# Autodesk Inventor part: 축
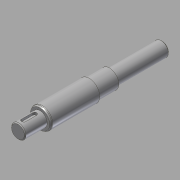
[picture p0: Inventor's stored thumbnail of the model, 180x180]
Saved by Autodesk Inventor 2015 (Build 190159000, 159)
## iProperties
Created: 2019-01
Part Number: 축
Material: 강철, 탄소
Document SubType Name: Modeling
Designer: mduedu
Density: 7.87 g/cm^3
Mass: 452.778 g
Surface Area: 120.904 cm^2
Volume: 57.5322 cm^3
Appearance: 강철
Author: mduedu
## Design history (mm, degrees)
sketch "스케치1"
  geometry: L1 (0, 0)-(26, 0); L2 (26, 0)-(26, 8.5); L3 (26, 8.5)-(0, 8.5); L4 (0, 8.5)-(0, 0); L5 (26, 0)-(84, 0); L6 (84, 0)-(84, 12.5); L7 (84, 12.5)-(26, 12.5); L8 (26, 12.5)-(26, 0); L9 (84, 0)-(108, 0); L10 (108, 0)-(108, 11); L11 (108, 11)-(84, 11); L12 (84, 11)-(84, 0); L13 (108, 0)-(170, 0); L14 (170, 0)-(170, 8.5); L15 (170, 8.5)-(108, 8.5); L16 (108, 8.5)-(108, 0)
  constraints: 32 end point, 8 parallel, 4 horizontal, 4 perpendicular
  dimensions: "d0" = 170 distance between parallel lines of L14 L4; "d2" = 26 distance of L2.end L3.end; "d3" = 24 distance of L10.end L11.end; "d4" = 62 distance of L14.end L15.end; "d5" = 17 diameter of L3 L1; "d6" = 25 diameter of L7 L5; "d7" = 22 diameter of L11 L9; "d8" = 17 diameter of L15 L13
revolve "회전1" sketch "스케치1" stored, may be unused: angle "d9" = 90 deg
node "작업 평면1"
sketch "스케치2" dims "d13" = 18
  geometry: L1 (6.5, -2.5)-(-6.5, -2.5); L2 (-6.5, -2.5)-(-6.5, 2.5); L3 (-6.5, 2.5)-(6.5, 2.5); L4 (6.5, 2.5)-(6.5, -2.5); L5 (13, 8.5)-(13, -8.5) reference; 3 further points
  constraints: 8 end point, 2 midpoint, 2 parallel, 2 vertical alignment, 1 horizontal, 1 horizontal alignment, 1 perpendicular, 4 other
  dimensions: "d10" = 5 distance between parallel lines of L3 L1; "d12" = 4 dimension on L5
extrude "돌출1" cut sketch "스케치2" distance "d14" = 3; taper "d15" = 0 deg
node "작업 평면2"
sketch "스케치3" dims "d19" = 18
  geometry: L1 (-24.5, -2.5)-(-11.5, -2.5); L2 (-11.5, -2.5)-(-11.5, 2.5); L3 (-11.5, 2.5)-(-24.5, 2.5); L4 (-24.5, 2.5)-(-24.5, -2.5); L5 (-31, 8.5)-(-31, -8.5) reference; 3 further points
  constraints: 8 end point, 2 midpoint, 2 parallel, 2 vertical alignment, 1 horizontal, 1 horizontal alignment, 1 perpendicular, 4 other
  dimensions: "d16" = 5 distance between parallel lines of L3 L1; "d18" = 4 dimension on L5
extrude "돌출2" cut sketch "스케치3" distance "d20" = 3; taper "d21" = 0 deg
chamfer "모따기1" distance "d22" = 1; stored, may be unused: second distance "d23" = 2, angle "d24" = 45 deg
chamfer "모따기2" distance "d25" = 2; stored, may be unused: second distance "d26" = 2, angle "d27" = 30 deg
fillet "모깎기2" dims "d30" = 2
node "솔리드1"
